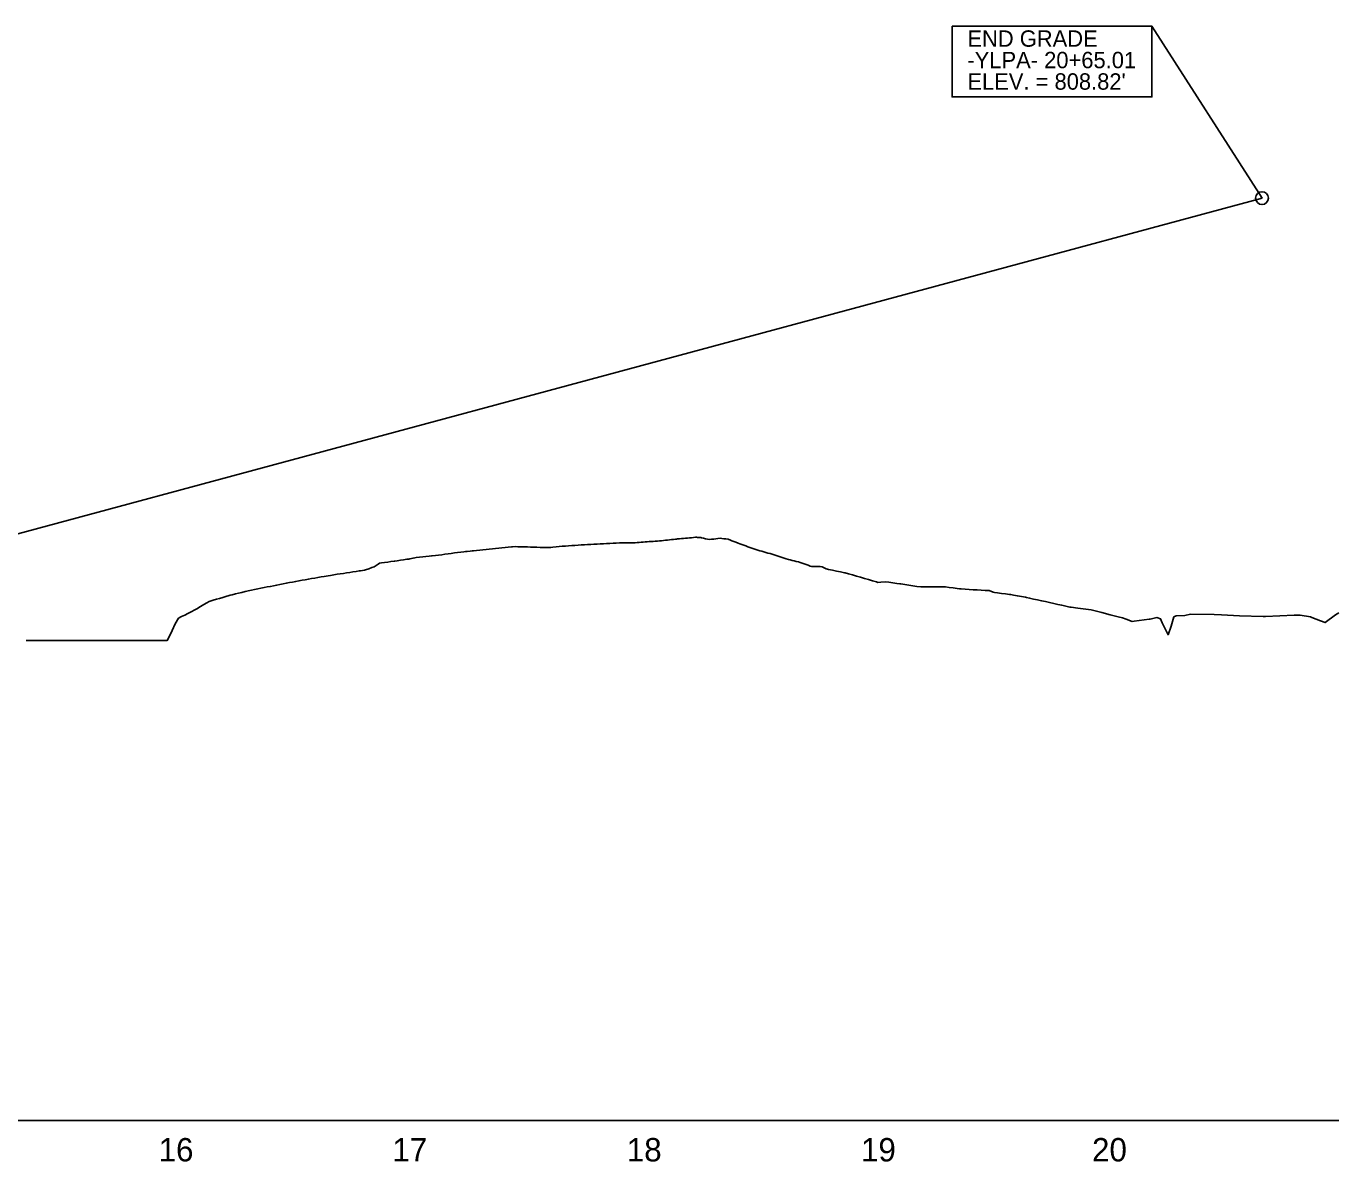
# Model space of a CAD drawing. Extents: x 579185 to 595036, y -53221 to -44640.
# Drawn here: x 579828 to 580388, y -51053 to -50568 of the extents above; entities that cross this region are included whole.
import ezdxf

# ---------------------------------------------------------------- set-up
doc = ezdxf.new("R2010")
doc.units = 0
for name, color, linetype in [('Exist Profile Cell', 7, 'Continuous'), ('Exist Vertical Profile Ground Line', 7, 'Continuous'), ('Exist Vertical Profile Horizontal Axis Label Major', 7, 'Continuous'), ('Prop Grid Mask', 7, 'Continuous'), ('Prop Vertical Profile Curve Label', 7, 'Continuous'), ('Prop Vertical Profile Grade', 7, 'Continuous'), ('Prop VPI Label', 7, 'Continuous')]:
    doc.layers.add(name, color=color, linetype=linetype)

msp = doc.modelspace()

# ---------------------------------------------------------------- linework, layer by layer
at = {"layer": 'Exist Profile Cell'}
msp.add_line((579290.38, -51035.8), (580388.15, -51035.8), dxfattribs=at)
at = {"layer": 'Exist Vertical Profile Ground Line'}
for points in [[(580011.75, -50793.1), (580013.11, -50792.92), (580014.46, -50792.75), (580015.19, -50792.65), (580015.82, -50792.61), (580017.17, -50792.52), (580018.02, -50792.46), (580018.53, -50792.4), (580019.88, -50792.25), (580021.24, -50792.1), (580022.59, -50791.95), (580023.95, -50791.81), (580025.3, -50791.67), (580026.66, -50791.52), (580028.01, -50791.39), (580029.37, -50791.25), (580030.72, -50791.11), (580032.08, -50790.98), (580033.43, -50790.85), (580034.79, -50790.72), (580035.17, -50790.68), (580036.39, -50790.6), (580037.5, -50790.62), (580038.85, -50790.65), (580040.21, -50790.68), (580041.56, -50790.72), (580042.92, -50790.76), (580044.27, -50790.8), (580045.63, -50790.85), (580046.98, -50790.9), (580048.34, -50790.95), (580049.69, -50790.99), (580051.05, -50790.95), (580051.63, -50790.94), (580052.4, -50790.84), (580053.85, -50790.65), (580055.11, -50790.56), (580056.47, -50790.45), (580057.82, -50790.36), (580059.18, -50790.26), (580060.53, -50790.16), (580061.89, -50790.07), (580063.24, -50789.98), (580064.6, -50789.89), (580065.95, -50789.8), (580067.31, -50789.72), (580067.67, -50789.7), (580068.66, -50789.64), (580070.02, -50789.56), (580071.37, -50789.48), (580072.73, -50789.41), (580074.08, -50789.34), (580075.44, -50789.27), (580076.79, -50789.2), (580078.15, -50789.13), (580079.5, -50789.08), (580080.86, -50789.04), (580082.21, -50788.99), (580083.57, -50788.95), (580085, -50788.9), (580086.28, -50788.9), (580087.63, -50788.9), (580088.49, -50788.89), (580089.35, -50788.82), (580090.21, -50788.75), (580091.07, -50788.68), (580091.93, -50788.61), (580092.79, -50788.54), (580093.65, -50788.47), (580094.51, -50788.4), (580095.37, -50788.33), (580096.23, -50788.26), (580097.09, -50788.19), (580097.95, -50788.13), (580098.8, -50788.06), (580099.66, -50787.99), (580100.52, -50787.9), (580101.38, -50787.8), (580102.24, -50787.7), (580103.1, -50787.6), (580103.96, -50787.5), (580104.82, -50787.41), (580105.34, -50787.35), (580105.68, -50787.31), (580106.54, -50787.23), (580107.4, -50787.15), (580108.26, -50787.08), (580109.12, -50787), (580109.98, -50786.92), (580110.84, -50786.85), (580111.7, -50786.77), (580112.55, -50786.7), (580113.41, -50786.62), (580113.75, -50786.6), (580114.27, -50786.64), (580115.13, -50786.7), (580115.61, -50786.74), (580115.99, -50786.83), (580116.85, -50787.04), (580117.71, -50787.26), (580118.57, -50787.47)], [(580118.57, -50787.47), (580119.43, -50787.57), (580120.29, -50787.47), (580121.15, -50787.36), (580122.01, -50787.24), (580122.87, -50787.12), (580123.97, -50786.97), (580124.59, -50787.07), (580125.45, -50787.2), (580126.3, -50787.29), (580127.39, -50787.4), (580128.27, -50787.8), (580128.88, -50788.05), (580129.74, -50788.38), (580130.6, -50788.72), (580131.67, -50789.15), (580132.32, -50789.38), (580133.18, -50789.69), (580134.04, -50789.99), (580134.9, -50790.3), (580135.76, -50790.61), (580136.62, -50790.92), (580137.48, -50791.24), (580138.34, -50791.55), (580138.73, -50791.7), (580139.2, -50791.83), (580140.05, -50792.08), (580140.91, -50792.32), (580141.77, -50792.57), (580142.63, -50792.82), (580143.49, -50793.07), (580144.35, -50793.33), (580145.21, -50793.58), (580146.07, -50793.84), (580146.61, -50794), (580146.93, -50794.1), (580147.79, -50794.38), (580148.65, -50794.66), (580149.51, -50794.94), (580150.37, -50795.23), (580151.23, -50795.51), (580152.09, -50795.8), (580153.06, -50796.12), (580153.8, -50796.29), (580154.66, -50796.49), (580155.52, -50796.69), (580156.38, -50796.89), (580157.35, -50797.11), (580158.1, -50797.37), (580158.96, -50797.67), (580159.82, -50797.97), (580160.68, -50798.27), (580161.54, -50798.57), (580162.4, -50798.87), (580162.93, -50799.06), (580163.26, -50799.08), (580164.12, -50799.12), (580164.98, -50799.13), (580165.84, -50799.13), (580166.7, -50799.14), (580167.55, -50799.21), (580168.41, -50799.61), (580169.27, -50800.01), (580169.8, -50800.25), (580170.13, -50800.32), (580171.85, -50800.67), (580173.57, -50801.02), (580175.29, -50801.38), (580177.01, -50801.74), (580177.35, -50801.81), (580178.73, -50802.2), (580180.45, -50802.69), (580182.16, -50803.19), (580183.88, -50803.68), (580185.6, -50804.18), (580187.32, -50804.68), (580189.04, -50805.19), (580190.76, -50805.69), (580191.28, -50805.85), (580192.48, -50805.76), (580194.42, -50805.62), (580195.91, -50805.82), (580197.63, -50806.05), (580199.35, -50806.28), (580200.67, -50806.46), (580201.07, -50806.52), (580202.79, -50806.77), (580204.51, -50807.03), (580206.23, -50807.29), (580207.95, -50807.56), (580209.66, -50807.8), (580211.38, -50807.8), (580213.1, -50807.8), (580214.82, -50807.8), (580216.54, -50807.8), (580218.26, -50807.81), (580220.14, -50807.82), (580221.7, -50808.03), (580223.41, -50808.27), (580225.13, -50808.5), (580226.11, -50808.64)], [(579892.51, -50821.16), (579893.86, -50820.49), (579895.22, -50819.81), (579896.57, -50819.14), (579898.23, -50818.33), (579899.28, -50817.73), (579900.64, -50816.96), (579901.68, -50816.38), (579901.99, -50816.19), (579903.35, -50815.39), (579904.7, -50814.6), (579905.65, -50814.04), (579906.06, -50813.92), (579907.41, -50813.51), (579908.77, -50813.1), (579910.12, -50812.69), (579911.48, -50812.28), (579912.83, -50811.88), (579914.19, -50811.48), (579914.63, -50811.35), (579915.54, -50811.13), (579916.9, -50810.8), (579918.25, -50810.47), (579919.61, -50810.14), (579920.96, -50809.82), (579921.73, -50809.64), (579922.32, -50809.51), (579923.67, -50809.23), (579925.03, -50808.94), (579926.38, -50808.66), (579927.74, -50808.38), (579929.09, -50808.11), (579930.45, -50807.83), (579931.8, -50807.56), (579933.16, -50807.29), (579934.51, -50807.02), (579935.87, -50806.76), (579937.22, -50806.5), (579938.58, -50806.24), (579939.93, -50805.98), (579941.29, -50805.73), (579942.64, -50805.48), (579944, -50805.23), (579945.35, -50804.98), (579946.71, -50804.73), (579948.06, -50804.49), (579949.42, -50804.25), (579950.77, -50804.02), (579952.13, -50803.78), (579953.48, -50803.55), (579954.84, -50803.32), (579956.48, -50803.05), (579957.55, -50802.87), (579958.9, -50802.65), (579960.26, -50802.43), (579961.61, -50802.22), (579962.97, -50802.01), (579964.32, -50801.8), (579965.68, -50801.59), (579967.03, -50801.39), (579968.39, -50801.18), (579969.74, -50800.99), (579970.29, -50800.91), (579971.1, -50800.8), (579972.03, -50800.68), (579972.45, -50800.52), (579973.81, -50800.04), (579975.16, -50799.57), (579976.16, -50799.22), (579976.52, -50798.97), (579977.87, -50798.02), (579978.45, -50797.61), (579979.23, -50797.51), (579980.58, -50797.34), (579981.94, -50797.17), (579983.29, -50797), (579984.65, -50796.83), (579984.97, -50796.78), (579986, -50796.62), (579987.36, -50796.42), (579988.71, -50796.22), (579990.07, -50796.01), (579990.87, -50795.9), (579991.42, -50795.78), (579992.78, -50795.48), (579993.54, -50795.32), (579994.14, -50795.26), (579995.49, -50795.11), (579996.85, -50794.97), (579998.2, -50794.83), (579999.56, -50794.69), (580000.61, -50794.59), (580000.91, -50794.55), (580002.27, -50794.38), (580003.63, -50794.22), (580004.98, -50794.03), (580006.33, -50793.84), (580007.69, -50793.65), (580009.04, -50793.46), (580010.4, -50793.28), (580011.75, -50793.1)], [(580226.11, -50808.64), (580226.85, -50808.69), (580228.57, -50808.81), (580230.29, -50808.92), (580232.01, -50809.01), (580233.73, -50809.1), (580235.45, -50809.19), (580237.16, -50809.29), (580238.88, -50809.39), (580240.6, -50810.03), (580241.16, -50810.23), (580242.32, -50810.38), (580244.04, -50810.6), (580245.76, -50810.81), (580247.48, -50811.03), (580248.1, -50811.11), (580249.2, -50811.31), (580250.91, -50811.62), (580252.63, -50811.93), (580254.35, -50812.24), (580254.79, -50812.32), (580256.07, -50812.6), (580257.79, -50812.98), (580259.51, -50813.36), (580261.23, -50813.73), (580262.95, -50814.11), (580264.66, -50814.49), (580266.38, -50814.87), (580268.1, -50815.25), (580268.94, -50815.43), (580269.82, -50815.63), (580271.54, -50816.01), (580273.26, -50816.39), (580273.81, -50816.51), (580276.7, -50816.89), (580280.13, -50817.33), (580282.39, -50817.63), (580283.57, -50817.93), (580287.01, -50818.8), (580290.45, -50819.68), (580293.88, -50820.56), (580295.81, -50821.05), (580297.32, -50821.59), (580299.88, -50822.52), (580300.76, -50822.41), (580307.18, -50821.64), (580307.63, -50821.54), (580310.4, -50820.94), (580312.05, -50821.38), (580312.76, -50823.18), (580315.28, -50828.23), (580316.52, -50824.58), (580317.72, -50820.63), (580318.7, -50820.15), (580322.41, -50820), (580324.83, -50819.51), (580334.98, -50819.58), (580338.05, -50819.71), (580345.81, -50820.22), (580355.82, -50820.47), (580356.84, -50820.39), (580369.16, -50819.85), (580369.81, -50819.84), (580371.73, -50819.93), (580376.06, -50820.59), (580376.65, -50820.85), (580380.34, -50822.26), (580382.31, -50823.02), (580386.81, -50819.8), (580388.14, -50818.91)], [(579827.46, -50830.66), (579828.82, -50830.66), (579829.18, -50830.66), (579830.17, -50830.66), (579831.53, -50830.66), (579832.88, -50830.66), (579834.24, -50830.66), (579835.21, -50830.66), (579835.59, -50830.66), (579836.95, -50830.66), (579838.3, -50830.66), (579839.66, -50830.66), (579841.02, -50830.66), (579842.37, -50830.66), (579842.92, -50830.66), (579843.73, -50830.66), (579845.08, -50830.66), (579846.44, -50830.66), (579847.79, -50830.66), (579849.15, -50830.66), (579850.5, -50830.66), (579851.86, -50830.66), (579853.21, -50830.66), (579854.57, -50830.66), (579855.92, -50830.66), (579856.6, -50830.66), (579857.28, -50830.66), (579858.63, -50830.66), (579860.12, -50830.66), (579861.34, -50830.66), (579861.82, -50830.66), (579862.7, -50830.66), (579864.05, -50830.66), (579865.41, -50830.66), (579866.76, -50830.66), (579868.12, -50830.66), (579869.73, -50830.66), (579870.83, -50830.66), (579871.3, -50830.66), (579872.18, -50830.66), (579873.54, -50830.66), (579874.89, -50830.66), (579876.25, -50830.66), (579877.6, -50830.66), (579878.96, -50830.66), (579880.31, -50830.66), (579881.67, -50830.66), (579883.02, -50830.66), (579884.38, -50830.66), (579885.73, -50830.66), (579887.22, -50830.66), (579887.78, -50830.66), (579888.44, -50829.37), (579889.8, -50826.47), (579891.15, -50823.57), (579892.51, -50821.16)]]:
    msp.add_lwpolyline(points, dxfattribs=at)
at = {"layer": 'Prop Grid Mask'}
msp.add_lwpolyline([(580222.98, -50568.23), (580308.37, -50568.23), (580308.37, -50598.42), (580222.98, -50598.42)], close=True, dxfattribs=at)
at = {"layer": 'Prop Vertical Profile Curve Label'}
msp.add_line((580355.39, -50641.67), (580308.37, -50568.23), dxfattribs=at)
at = {"layer": 'Prop Vertical Profile Grade'}
msp.add_line((579790.38, -50794.1), (580355.39, -50641.67), dxfattribs=at)
at = {"layer": 'Prop VPI Label'}
msp.add_circle((580355.39, -50641.67), 2.75, dxfattribs=at)

# ---------------------------------------------------------------- texts
at = {"layer": 'Exist Vertical Profile Horizontal Axis Label Major'}
for s, p in [('16', (579884.07, -51053.3)), ('17', (579983.92, -51053.3)), ('18', (580084.05, -51053.3)), ('19', (580184.09, -51053.3)), ('20', (580282.77, -51053.3))]:
    msp.add_text(s, height=10, dxfattribs=at).set_placement(p)
at = {"layer": 'Prop VPI Label'}
for s, p in [('END GRADE', (580229.53, -50576.99)), ('-YLPA- 20+65.01', (580229.53, -50586.17)), ("ELEV. = 808.82'", (580229.53, -50595.34))]:
    msp.add_text(s, height=7, dxfattribs=at).set_placement(p)

doc.saveas('drawing.dxf')
